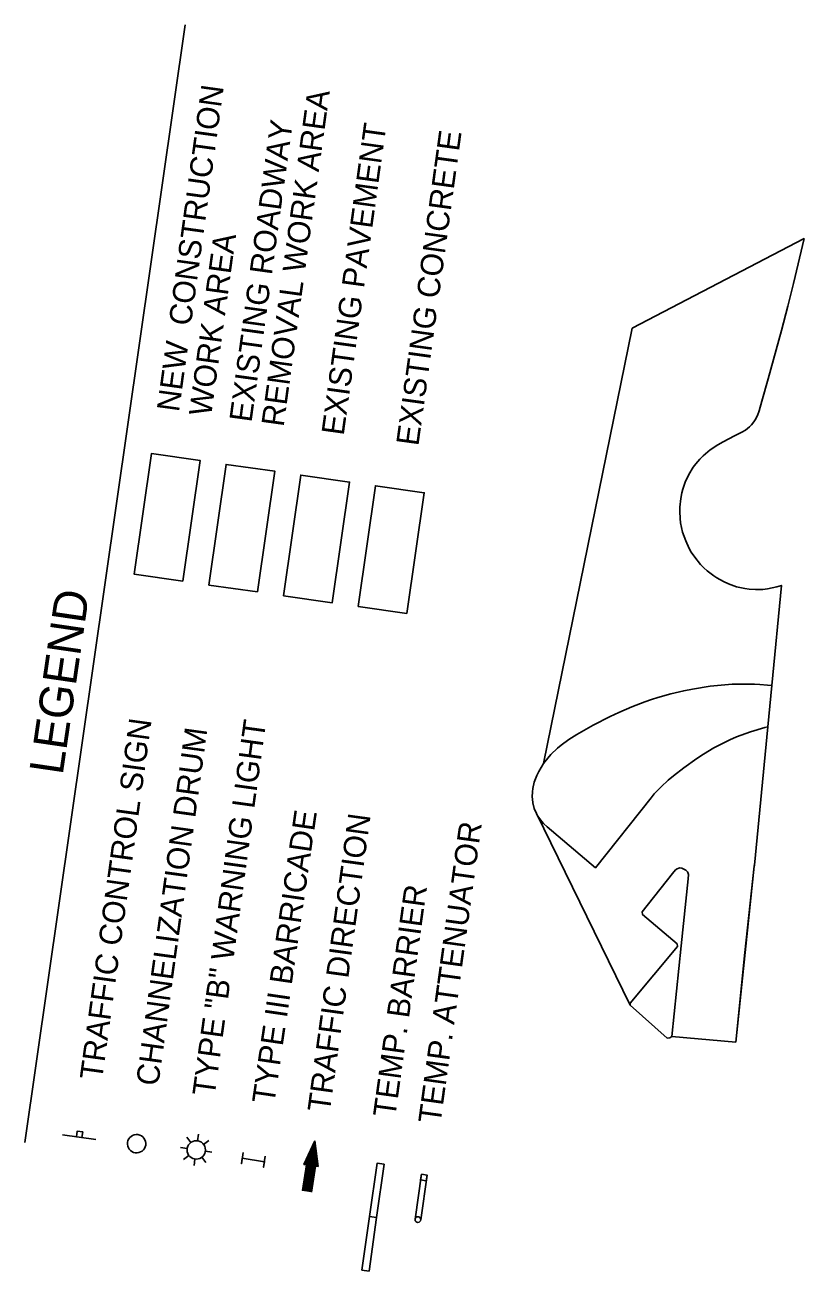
# Model space of a CAD drawing. Extents: x 1795987 to 1799700, y 243690 to 251545.
# Drawn here: x 1797501.1 to 1797771.3, y 249413.2 to 249845.4 of the extents above; entities that cross this region are included whole.
import ezdxf

# ---------------------------------------------------------------- set-up
doc = ezdxf.new("R2010")
doc.units = 0
for name, color, linetype in [('EP', 7, 'Continuous'), ('Level 23', 7, 'Continuous'), ('Level 31', 7, 'Continuous'), ('Prop_Horiz Alignment', 7, 'Continuous')]:
    doc.layers.add(name, color=color, linetype=linetype)

# ---------------------------------------------------------------- blocks, each defined once
blk = doc.blocks.new('T21LR')
at = {"layer": 'Level 23'}
for p, q in [((0, 2), (31.5, 2)), ((0, -2), (31.5, -2))]:
    blk.add_line(p, q, dxfattribs=at)
blk.add_lwpolyline([(0, -2), (4, -2), (4, 2), (0, 2)], close=True, dxfattribs=at)
blk.add_circle((31.5, 0), 2, dxfattribs=at)

msp = doc.modelspace()

# ---------------------------------------------------------------- linework, layer by layer
at = {"layer": 'EP'}
for points in [[(1797729.6, 249614.5), (1797725.06, 249613.43), (1797720.59, 249612.17), (1797718.38, 249611.46), (1797716.07, 249610.65), (1797711.53, 249608.88), (1797707.05, 249606.92), (1797704.09, 249605.52), (1797698.21, 249602.54), (1797692.46, 249599.33), (1797689.69, 249597.57), (1797687.07, 249595.64), (1797685.82, 249594.61), (1797683.49, 249592.39), (1797682.41, 249591.18), (1797680.92, 249589.25), (1797679.27, 249586.52), (1797678.58, 249585.08), (1797677.76, 249582.84), (1797677.23, 249580.56), (1797677.08, 249579.4), (1797677.03, 249577.7), (1797677.08, 249576.85), (1797677.24, 249575.59), (1797677.73, 249573.72), (1797678.5, 249571.91), (1797679, 249571.02), (1797680.23, 249569.31), (1797680.97, 249568.49), (1797682.23, 249567.3), (1797698.94, 249553.14), (1797718.23, 249577.4), (1797719.34, 249578.73), (1797721.7, 249581.22), (1797724.22, 249583.54)], [(1797727.35, 249526.78), (1797715.33, 249536.89), (1797715.13, 249537.81), (1797725.68, 249551.14), (1797726.77, 249552.38), (1797727.3, 249552.78), (1797727.88, 249553), (1797728.19, 249553.03), (1797728.91, 249552.95), (1797729.88, 249552.56), (1797730.32, 249552.27), (1797730.86, 249551.75), (1797731.04, 249551.46), (1797731.22, 249550.83), (1797731.14, 249549.3), (1797728.72, 249526.01), (1797725.49, 249494.54), (1797724.72, 249494.11), (1797723.88, 249494.06), (1797711.05, 249505.41), (1797710.99, 249506.18), (1797727.39, 249525.78), (1797727.35, 249526.78)]]:
    msp.add_lwpolyline(points, dxfattribs=at)
at = {"layer": 'Level 31'}
for p, q in [((1797501.08, 249457.88), (1797556.62, 249845.43)), ((1797560.96, 249458.42), (1797561.29, 249460.71)), ((1797525.67, 249458.85), (1797514.09, 249460.51)), ((1797558.59, 249457.81), (1797557.21, 249459.66)), ((1797564.91, 249458.56), (1797563.07, 249457.17)), ((1797601.64, 249458.41), (1797597.82, 249450.25)), ((1797602.77, 249449.47), (1797601.64, 249458.41)), ((1797557.35, 249455.71), (1797555.06, 249456.04)), ((1797556.1, 249451.96), (1797557.95, 249453.34)), ((1797560.06, 249452.09), (1797559.73, 249449.81)), ((1797563.81, 249450.85), (1797562.42, 249452.7)), ((1797563.67, 249454.8), (1797565.96, 249454.48)), ((1797598.75, 249450.1), (1797597.35, 249441.13)), ((1797597.82, 249450.25), (1797598.75, 249450.1)), ((1797600.43, 249440.65), (1797601.84, 249449.62)), ((1797601.84, 249449.62), (1797602.77, 249449.47))]:
    msp.add_line(p, q, dxfattribs=at)
for points in [[(1797555.87, 249652.47), (1797561.87, 249694.32), (1797544.97, 249696.74), (1797538.97, 249654.89)], [(1797581.77, 249648.76), (1797587.77, 249690.61), (1797570.87, 249693.03), (1797564.87, 249651.18)], [(1797607.67, 249645.05), (1797613.66, 249686.89), (1797596.77, 249689.32), (1797590.77, 249647.47)], [(1797633.57, 249641.34), (1797639.56, 249683.18), (1797622.67, 249685.6), (1797616.67, 249643.76)], [(1797518.91, 249459.82), (1797519.19, 249461.75), (1797521.12, 249461.47), (1797520.84, 249459.54)], [(1797625.73, 249450.35), (1797623.26, 249450.71), (1797620.6, 249432.15), (1797623.07, 249431.79)], [(1797623.07, 249431.79), (1797620.6, 249432.15), (1797617.94, 249413.59), (1797620.42, 249413.23)]]:
    msp.add_lwpolyline(points, close=True, dxfattribs=at)
for points in [[(1797600.7, 249456.4), (1797598.28, 249440.98)], [(1797601.09, 249457.24), (1797598.54, 249440.94)], [(1797601.49, 249458.09), (1797598.79, 249440.9)], [(1797601.71, 249457.83), (1797599.05, 249440.86)], [(1797601.83, 249456.9), (1797599.31, 249440.82)], [(1797584.46, 249453.09), (1797583.84, 249449.24), (1797584.15, 249451.17), (1797576.45, 249452.4), (1797576.14, 249450.48), (1797576.75, 249454.33)], [(1797599.51, 249453.85), (1797597.51, 249441.1)], [(1797599.9, 249454.7), (1797597.77, 249441.06)], [(1797600.3, 249455.55), (1797598.02, 249441.02)], [(1797598.72, 249452.16), (1797598.4, 249450.16)], [(1797599.11, 249453), (1797598.66, 249450.12)], [(1797601.95, 249455.97), (1797599.56, 249440.78)], [(1797602.06, 249455.04), (1797599.82, 249440.74)], [(1797602.18, 249454.11), (1797600.08, 249440.7)], [(1797602.3, 249453.19), (1797600.33, 249440.66)], [(1797602.42, 249452.26), (1797602, 249449.59)], [(1797597.92, 249450.46), (1797597.89, 249450.24)], [(1797598.32, 249451.31), (1797598.15, 249450.2)], [(1797602.53, 249451.33), (1797602.25, 249449.55)], [(1797602.65, 249450.4), (1797602.51, 249449.51)]]:
    msp.add_lwpolyline(points, dxfattribs=at)
msp.add_circle((1797560.51, 249455.26), 3.19, dxfattribs=at)
for start, end in [(81.8439, 261.8439), (261.8439, 81.8439)]:
    msp.add_arc((1797539.82, 249457.4), 3.18, start, end, dxfattribs=at)
at = {"layer": 'Prop_Horiz Alignment'}
for p, q in [((1797771.32, 249771.31), (1797711.7, 249740.2)), ((1797711.7, 249740.2), (1797680.92, 249589.25)), ((1797760.13, 249616.35), (1797763.47, 249651.01)), ((1797758.75, 249602.03), (1797760.13, 249616.35)), ((1797754.12, 249554.04), (1797758.75, 249602.03)), ((1797678.5, 249571.91), (1797711.05, 249505.41)), ((1797747.61, 249492.58), (1797754.06, 249553.61)), ((1797754.06, 249553.61), (1797754.12, 249554.04)), ((1797725.49, 249494.54), (1797747.61, 249492.58))]:
    msp.add_line(p, q, dxfattribs=at)
for points in [[(1797771.32, 249771.31), (1797711.7, 249740.2), (1797680.92, 249589.25), (1797682.41, 249591.18), (1797683.49, 249592.39), (1797685.82, 249594.61), (1797687.07, 249595.64), (1797689.69, 249597.57), (1797692.46, 249599.33), (1797698.21, 249602.54), (1797704.09, 249605.52), (1797707.05, 249606.92), (1797711.53, 249608.88), (1797716.07, 249610.65), (1797718.38, 249611.46), (1797720.59, 249612.17), (1797725.06, 249613.43), (1797729.6, 249614.5), (1797732.65, 249615.1), (1797738.79, 249616.05), (1797743.87, 249616.57), (1797746.41, 249616.73), (1797750.24, 249616.83), (1797754.08, 249616.74), (1797756.01, 249616.62), (1797758.67, 249616.42), (1797760.12, 249616.35), (1797763.47, 249651.01), (1797761.9, 249650.54), (1797758.61, 249649.86), (1797756.96, 249649.67), (1797754.46, 249649.59), (1797752.26, 249649.73), (1797750.8, 249649.93), (1797747.93, 249650.57), (1797745.15, 249651.54), (1797743.36, 249652.35), (1797741.07, 249653.62), (1797739.98, 249654.34), (1797737.65, 249656.15), (1797736.56, 249657.14), (1797735.43, 249658.3), (1797733.39, 249660.81), (1797732.2, 249662.61), (1797731.49, 249663.86), (1797730.26, 249666.47), (1797729.19, 249669.53), (1797728.5, 249672.69), (1797728.29, 249674.3), (1797728.17, 249676.73), (1797728.2, 249678.21), (1797728.52, 249681.16), (1797728.91, 249683.1), (1797729.25, 249684.37), (1797730.11, 249686.86), (1797731.34, 249689.53), (1797732.86, 249692.03), (1797733.72, 249693.2), (1797735.13, 249694.84), (1797736.27, 249695.97), (1797738.75, 249698.01), (1797741.44, 249699.8), (1797743.31, 249700.88), (1797747.15, 249702.86), (1797749.73, 249704.17), (1797750.96, 249704.93), (1797752.4, 249706.07), (1797753.05, 249706.71), (1797753.91, 249707.77), (1797754.37, 249708.48), (1797755.14, 249709.99), (1797755.73, 249711.59), (1797756.67, 249714.92), (1797758.86, 249722.64), (1797763.53, 249739.46), (1797765.74, 249747.92), (1797767.68, 249755.71), (1797771.32, 249771.31)], [(1797763.47, 249651.01), (1797761.9, 249650.54), (1797758.61, 249649.86), (1797756.96, 249649.67), (1797754.46, 249649.59), (1797752.26, 249649.73), (1797750.8, 249649.93), (1797747.93, 249650.57), (1797745.15, 249651.54), (1797743.36, 249652.35), (1797741.07, 249653.62), (1797739.98, 249654.34), (1797737.65, 249656.15), (1797736.56, 249657.14), (1797735.43, 249658.3), (1797733.39, 249660.81), (1797732.2, 249662.61), (1797731.49, 249663.86), (1797730.26, 249666.47), (1797729.19, 249669.53), (1797728.5, 249672.69), (1797728.29, 249674.3), (1797728.17, 249676.73), (1797728.2, 249678.21), (1797728.52, 249681.16), (1797728.91, 249683.1), (1797729.25, 249684.37), (1797730.11, 249686.86), (1797731.34, 249689.53), (1797732.86, 249692.03), (1797733.72, 249693.2), (1797735.13, 249694.84), (1797736.27, 249695.97), (1797738.75, 249698.01), (1797741.44, 249699.8), (1797743.31, 249700.88), (1797747.15, 249702.86), (1797749.73, 249704.17), (1797750.96, 249704.93), (1797752.4, 249706.07), (1797753.05, 249706.71), (1797753.91, 249707.77), (1797754.37, 249708.48), (1797755.14, 249709.99), (1797755.73, 249711.59), (1797756.67, 249714.92), (1797758.86, 249722.64), (1797763.53, 249739.46), (1797765.74, 249747.92), (1797767.68, 249755.71), (1797771.32, 249771.31)], [(1797590.77, 249647.47), (1797607.67, 249645.05), (1797613.66, 249686.89), (1797596.77, 249689.32), (1797590.77, 249647.47)], [(1797760.12, 249616.35), (1797758.67, 249616.42), (1797756.01, 249616.62), (1797754.08, 249616.74), (1797750.24, 249616.83), (1797746.41, 249616.73), (1797743.87, 249616.57), (1797738.79, 249616.05), (1797732.65, 249615.1), (1797729.6, 249614.5), (1797725.06, 249613.43), (1797720.59, 249612.17), (1797718.38, 249611.46), (1797716.07, 249610.65), (1797711.53, 249608.88), (1797707.05, 249606.92), (1797704.09, 249605.52), (1797698.21, 249602.54), (1797692.46, 249599.33), (1797689.69, 249597.57), (1797687.07, 249595.64), (1797685.82, 249594.61), (1797683.49, 249592.39), (1797682.41, 249591.18), (1797680.92, 249589.25)], [(1797758.75, 249602.03), (1797757.66, 249601.76), (1797752.72, 249600.3), (1797747.91, 249598.51), (1797745.56, 249597.49), (1797743.7, 249596.6), (1797740.05, 249594.65), (1797736.49, 249592.52), (1797734.17, 249591), (1797729.62, 249587.8), (1797725.98, 249585.01), (1797724.22, 249583.54), (1797721.7, 249581.22), (1797719.34, 249578.73), (1797718.23, 249577.4), (1797698.94, 249553.14), (1797682.23, 249567.3), (1797680.97, 249568.49), (1797680.23, 249569.31), (1797679, 249571.02), (1797678.5, 249571.91)], [(1797727.35, 249526.78), (1797715.33, 249536.89), (1797715.13, 249537.81), (1797725.68, 249551.14), (1797726.77, 249552.38), (1797727.3, 249552.78), (1797727.88, 249553), (1797728.19, 249553.03), (1797728.91, 249552.95), (1797729.88, 249552.56), (1797730.32, 249552.27), (1797730.86, 249551.75), (1797731.04, 249551.46), (1797731.22, 249550.83), (1797731.14, 249549.3), (1797728.72, 249526.01), (1797725.49, 249494.54)], [(1797747.61, 249492.58), (1797750.77, 249523.67), (1797754.06, 249553.61)], [(1797711.05, 249505.41), (1797710.99, 249506.18), (1797727.39, 249525.78), (1797727.35, 249526.78)]]:
    msp.add_lwpolyline(points, dxfattribs=at)

# ---------------------------------------------------------------- block references
at = {"layer": 'Level 31', "xscale": 0.5000000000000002, "yscale": 0.5000000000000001, "rotation": -98.00678026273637}
msp.add_blockref('T21LR', (1797639.57, 249446.69), dxfattribs=at)

# ---------------------------------------------------------------- texts
at = {"layer": 'Level 31'}
for s, height, rotation, p in [('NEW  CONSTRUCTION', 7.7999, 82.1569, (1797554.51, 249710.98)), ('REMOVAL WORK AREA', 7.7999, 82.1569, (1797590.79, 249705.84)), ('EXISTING ROADWAY', 7.7999, 82.1569, (1797579.66, 249707.38)), ('EXISTING PAVEMENT', 7.7999, 82.1569, (1797611.62, 249702.81)), ('EXISTING CONCRETE', 7.7999, 82.1569, (1797637.53, 249699.18)), ('WORK AREA', 7.8, 82.1569, (1797565.64, 249709.45)), ('LEGEND', 11.7, 81.6779, (1797514.15, 249585.02)), ('TRAFFIC CONTROL SIGN', 7.7999, 82.1569, (1797527.81, 249479.22)), ('TYPE "B" WARNING LIGHT', 7.7999, 82.1569, (1797566.85, 249473.62)), ('CHANNELIZATION DRUM', 7.7999, 82.1569, (1797547.3, 249477.17)), ('TYPE III BARRICADE', 7.7999, 81.6779, (1797587.54, 249470.96)), ('TRAFFIC DIRECTION', 7.7999, 82.1569, (1797606.79, 249468.03)), ('TEMP. ATTENUATOR', 7.7999, 82.1569, (1797645.19, 249464.08)), ('TEMP. BARRIER', 7.7999, 82.1569, (1797629.51, 249466.28))]:
    msp.add_text(s, height=height, rotation=rotation, dxfattribs=at).set_placement(p)

doc.saveas('drawing.dxf')
